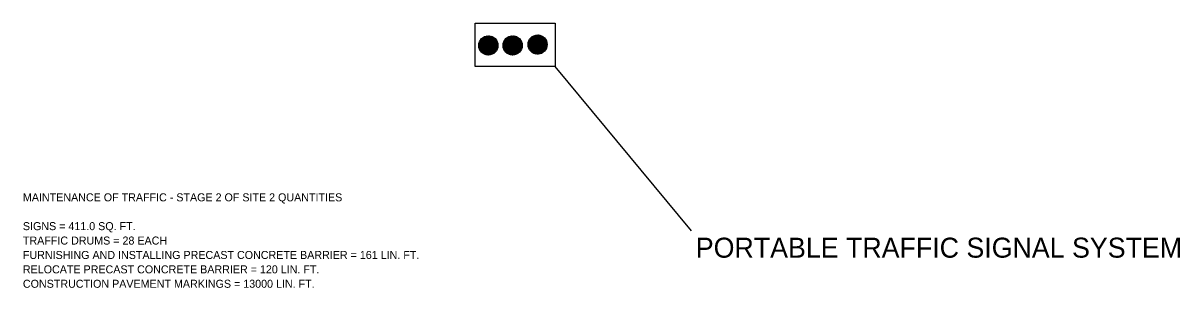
# Model space of a CAD drawing. Extents: x 1678017 to 1687792, y 404433 to 413488.
# Drawn here: x 1683447 to 1684314, y 409252 to 409451 of the extents above; entities that cross this region are included whole.
import ezdxf

# ---------------------------------------------------------------- set-up
doc = ezdxf.new("R2010")
doc.units = 0
doc.layers.add('Default', color=7, linetype='Continuous')
doc.layers.add('S_MSC_PT_SYM', color=7, linetype='Continuous')

msp = doc.modelspace()

# ---------------------------------------------------------------- linework, layer by layer
at = {"layer": 'Default'}
for p, q in [((1683791, 409439.5), (1683801.16, 409429.34)), ((1683791.24, 409439.7), (1683801.36, 409429.58)), ((1683791.48, 409439.9), (1683801.56, 409429.82)), ((1683791.74, 409440.09), (1683801.75, 409430.08)), ((1683792.01, 409440.26), (1683801.92, 409430.35)), ((1683792.28, 409440.43), (1683802.09, 409430.62)), ((1683792.57, 409440.58), (1683802.24, 409430.91)), ((1683792.87, 409440.73), (1683802.39, 409431.21)), ((1683793.18, 409440.86), (1683802.52, 409431.52)), ((1683793.5, 409440.98), (1683802.64, 409431.84)), ((1683793.83, 409441.09), (1683802.75, 409432.17)), ((1683794.18, 409441.18), (1683802.84, 409432.52)), ((1683794.55, 409441.26), (1683802.92, 409432.89)), ((1683794.93, 409441.32), (1683802.98, 409433.27)), ((1683795.33, 409441.36), (1683803.02, 409433.67)), ((1683795.76, 409441.37), (1683803.03, 409434.1)), ((1683796.21, 409441.37), (1683803.03, 409434.55)), ((1683796.69, 409441.33), (1683802.99, 409435.03)), ((1683797.21, 409441.24), (1683802.9, 409435.55)), ((1683797.79, 409441.11), (1683802.77, 409436.13)), ((1683798.45, 409440.89), (1683802.55, 409436.79)), ((1683799.28, 409440.5), (1683802.16, 409437.62)), ((1683809.28, 409439.59), (1683819.42, 409429.45)), ((1683809.52, 409439.79), (1683819.63, 409429.69)), ((1683809.77, 409439.98), (1683819.82, 409429.94)), ((1683810.03, 409440.16), (1683820, 409430.2)), ((1683810.3, 409440.34), (1683820.17, 409430.47)), ((1683810.58, 409440.5), (1683820.33, 409430.75)), ((1683810.87, 409440.65), (1683820.48, 409431.04)), ((1683811.18, 409440.79), (1683820.62, 409431.34)), ((1683811.49, 409440.91), (1683820.75, 409431.66)), ((1683811.82, 409441.03), (1683820.86, 409431.98)), ((1683812.16, 409441.13), (1683820.96, 409432.33)), ((1683812.52, 409441.21), (1683821.05, 409432.68)), ((1683812.89, 409441.28), (1683821.12, 409433.05)), ((1683813.28, 409441.34), (1683821.17, 409433.44)), ((1683813.69, 409441.37), (1683821.2, 409433.86)), ((1683814.13, 409441.37), (1683821.21, 409434.29)), ((1683814.59, 409441.35), (1683821.19, 409434.75)), ((1683815.09, 409441.29), (1683821.13, 409435.25)), ((1683815.63, 409441.19), (1683821.03, 409435.8)), ((1683816.25, 409441.02), (1683820.86, 409436.41)), ((1683816.97, 409440.74), (1683820.58, 409437.13)), ((1683817.94, 409440.22), (1683820.05, 409438.1)), ((1683827.33, 409439.58), (1683837.47, 409429.44)), ((1683827.54, 409439.81), (1683837.7, 409429.65)), ((1683827.76, 409440.04), (1683837.93, 409429.87)), ((1683827.99, 409440.25), (1683838.14, 409430.1)), ((1683828.23, 409440.45), (1683838.34, 409430.34)), ((1683828.48, 409440.64), (1683838.53, 409430.59)), ((1683828.74, 409440.82), (1683838.71, 409430.85)), ((1683829.01, 409440.99), (1683838.88, 409431.12)), ((1683829.3, 409441.16), (1683839.05, 409431.41)), ((1683829.59, 409441.31), (1683839.2, 409431.7)), ((1683829.89, 409441.45), (1683839.33, 409432)), ((1683830.2, 409441.57), (1683839.46, 409432.31)), ((1683830.53, 409441.69), (1683839.58, 409432.64)), ((1683830.87, 409441.79), (1683839.68, 409432.98)), ((1683831.23, 409441.87), (1683839.76, 409433.34)), ((1683831.6, 409441.94), (1683839.83, 409433.71)), ((1683831.99, 409441.99), (1683839.88, 409434.1)), ((1683832.4, 409442.02), (1683839.91, 409434.51)), ((1683832.84, 409442.03), (1683839.92, 409434.95)), ((1683833.3, 409442.01), (1683839.9, 409435.41)), ((1683833.8, 409441.95), (1683839.84, 409435.91)), ((1683834.35, 409441.85), (1683839.74, 409436.46)), ((1683834.96, 409441.68), (1683839.57, 409437.07)), ((1683835.68, 409441.4), (1683839.29, 409437.79)), ((1683836.65, 409440.87), (1683838.76, 409438.76)), ((1683788.66, 409434.33), (1683795.99, 409427)), ((1683788.67, 409433.88), (1683795.54, 409427.01)), ((1683788.68, 409434.75), (1683796.41, 409427.02)), ((1683788.7, 409433.4), (1683795.06, 409427.04)), ((1683788.72, 409435.15), (1683796.81, 409427.06)), ((1683788.78, 409432.88), (1683794.54, 409427.12)), ((1683788.79, 409435.53), (1683797.19, 409427.13)), ((1683788.86, 409435.89), (1683797.55, 409427.2)), ((1683788.91, 409432.31), (1683793.97, 409427.25)), ((1683788.96, 409436.24), (1683797.9, 409427.3)), ((1683789.07, 409436.57), (1683798.23, 409427.41)), ((1683789.12, 409431.66), (1683793.32, 409427.46)), ((1683789.32, 409437.2), (1683798.86, 409427.66)), ((1683789.47, 409437.5), (1683799.16, 409427.81)), ((1683789.48, 409430.86), (1683792.52, 409427.82)), ((1683789.62, 409437.78), (1683799.44, 409427.96)), ((1683789.79, 409438.06), (1683799.72, 409428.13)), ((1683789.97, 409438.32), (1683799.98, 409428.31)), ((1683790.16, 409438.58), (1683800.24, 409428.5)), ((1683790.35, 409438.82), (1683800.48, 409428.69)), ((1683790.56, 409439.06), (1683800.72, 409428.9)), ((1683790.78, 409439.28), (1683800.94, 409429.12)), ((1683806.84, 409434.51), (1683814.35, 409427.01)), ((1683806.84, 409434.08), (1683813.91, 409427)), ((1683806.86, 409433.62), (1683813.45, 409427.02)), ((1683806.87, 409434.93), (1683814.76, 409427.04)), ((1683806.92, 409435.32), (1683815.15, 409427.09)), ((1683806.92, 409433.12), (1683812.95, 409427.08)), ((1683806.99, 409435.69), (1683815.52, 409427.16)), ((1683807.02, 409432.57), (1683812.41, 409427.18)), ((1683807.08, 409436.05), (1683815.88, 409427.24)), ((1683807.18, 409436.39), (1683816.22, 409427.35)), ((1683807.19, 409431.96), (1683811.79, 409427.35)), ((1683807.29, 409436.71), (1683816.55, 409427.46)), ((1683807.42, 409437.03), (1683816.87, 409427.59)), ((1683807.47, 409431.24), (1683811.07, 409427.63)), ((1683807.56, 409437.33), (1683817.17, 409427.73)), ((1683807.71, 409437.62), (1683817.46, 409427.88)), ((1683807.87, 409437.91), (1683817.74, 409428.04)), ((1683808.04, 409438.18), (1683818.01, 409428.21)), ((1683808.23, 409438.44), (1683818.27, 409428.39)), ((1683808.42, 409438.69), (1683818.52, 409428.58)), ((1683808.62, 409438.93), (1683818.76, 409428.78)), ((1683808.83, 409439.16), (1683818.99, 409429)), ((1683809.05, 409439.38), (1683819.21, 409429.22)), ((1683825.55, 409434.74), (1683832.63, 409427.66)), ((1683825.56, 409435.17), (1683833.06, 409427.67)), ((1683825.57, 409434.27), (1683832.16, 409427.68)), ((1683825.59, 409435.58), (1683833.47, 409427.7)), ((1683825.63, 409433.77), (1683831.66, 409427.74)), ((1683825.64, 409435.97), (1683833.86, 409427.75)), ((1683825.71, 409436.35), (1683834.24, 409427.82)), ((1683825.73, 409433.23), (1683831.12, 409427.84)), ((1683825.79, 409436.7), (1683834.59, 409427.9)), ((1683825.89, 409437.05), (1683834.93, 409428)), ((1683825.9, 409432.62), (1683830.51, 409428.01)), ((1683826.01, 409437.37), (1683835.26, 409428.12)), ((1683826.13, 409437.69), (1683835.58, 409428.24)), ((1683826.18, 409431.9), (1683829.79, 409428.29)), ((1683826.27, 409437.99), (1683835.88, 409428.38)), ((1683826.42, 409438.28), (1683836.17, 409428.53)), ((1683826.58, 409438.56), (1683836.45, 409428.69)), ((1683826.71, 409430.92), (1683828.81, 409428.82)), ((1683826.76, 409438.83), (1683836.72, 409428.87)), ((1683826.94, 409439.09), (1683836.98, 409429.05)), ((1683827.13, 409439.34), (1683837.23, 409429.24)), ((1683790.44, 409429.46), (1683791.12, 409428.78)), ((1683808, 409430.26), (1683810.1, 409428.17))]:
    msp.add_line(p, q, dxfattribs=at)
msp.add_lwpolyline([(1683845.81, 409450.91), (1683845.81, 409418.43), (1683785.87, 409418.43), (1683785.87, 409450.91)], close=True, dxfattribs=at)
msp.add_lwpolyline([(1683948.18, 409295.11), (1683845.81, 409418.43)], dxfattribs=at)
for centre in [(1683795.85, 409434.19), (1683814.02, 409434.19), (1683832.74, 409434.85)]:
    msp.add_circle(centre, 7.19, dxfattribs=at)

# ---------------------------------------------------------------- texts
msp.add_text('PORTABLE TRAFFIC SIGNAL SYSTEM', height=15, dxfattribs=at).set_placement((1683951.31, 409275.04))
at = {"layer": 'S_MSC_PT_SYM'}
for s, p in [('MAINTENANCE OF TRAFFIC - STAGE 2 OF SITE 2 QUANTITIES', (1683446.96, 409317.28)), ('SIGNS = 411.0 SQ. FT.', (1683446.96, 409295.68)), ('TRAFFIC DRUMS = 28 EACH', (1683446.96, 409284.88)), ('FURNISHING AND INSTALLING PRECAST CONCRETE BARRIER = 161 LIN. FT.', (1683446.96, 409274.08)), ('RELOCATE PRECAST CONCRETE BARRIER = 120 LIN. FT.', (1683446.96, 409263.28)), ('CONSTRUCTION PAVEMENT MARKINGS = 13000 LIN. FT.', (1683446.96, 409252.48))]:
    msp.add_text(s, height=6, dxfattribs=at).set_placement(p)

doc.saveas('drawing.dxf')
